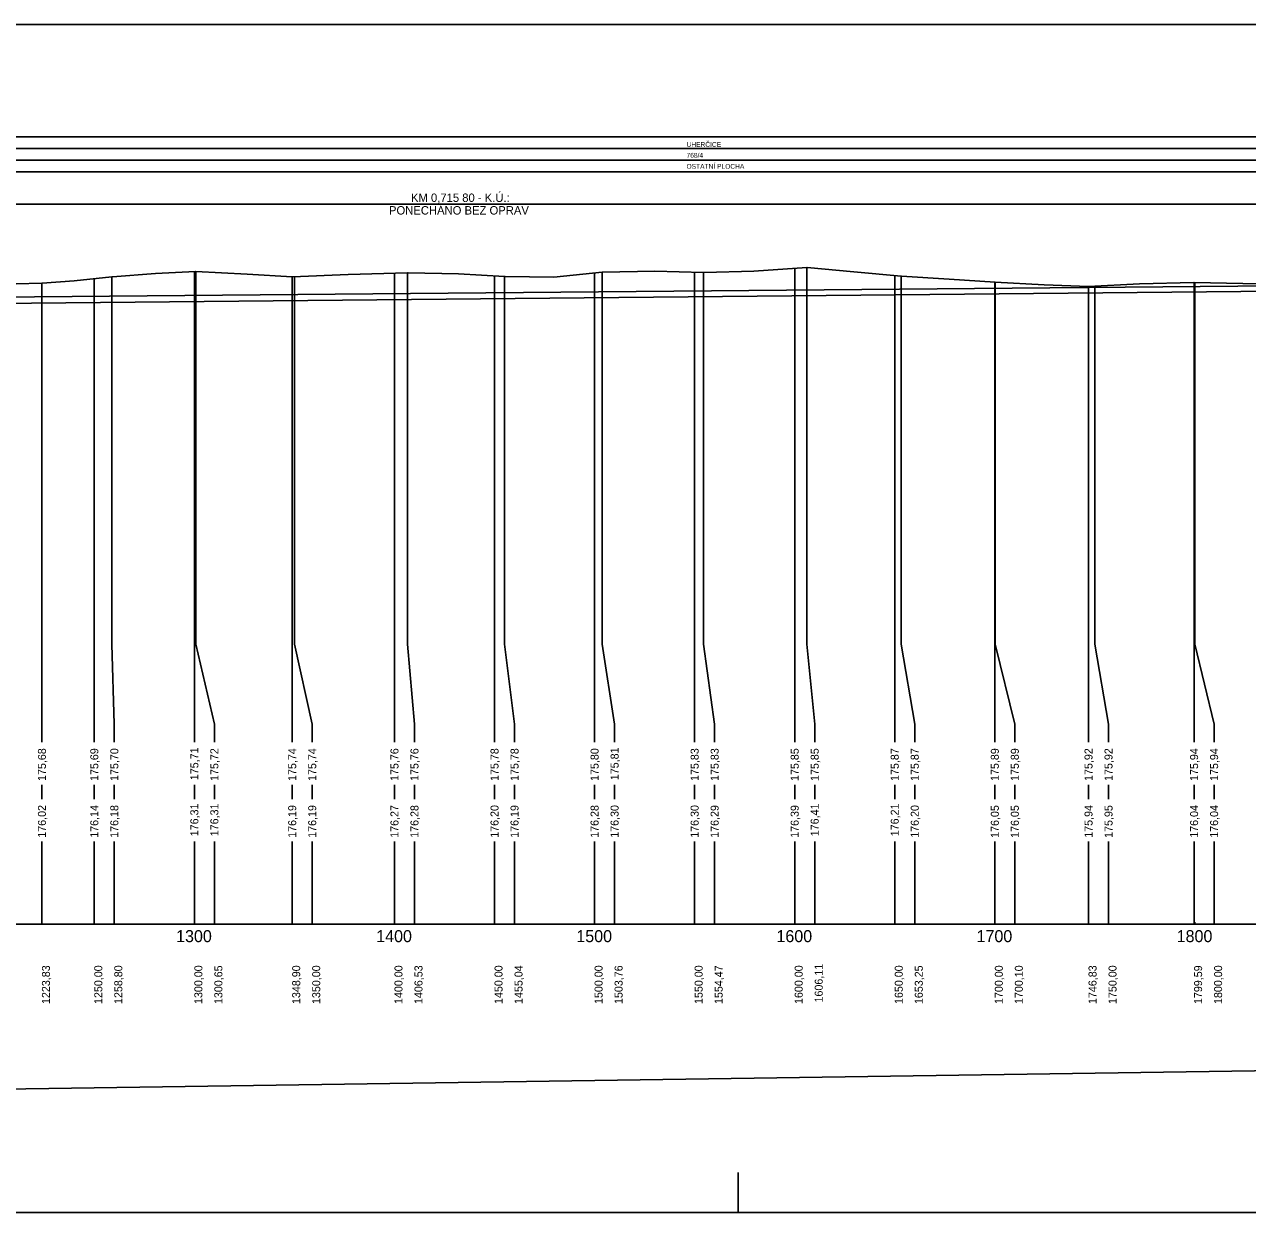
# Model space of a CAD drawing. Extents: x -614174 to -599765, y -1185887 to -1181080.
# Drawn here: x -608011 to -607400, y -1183702 to -1183108 of the extents above; entities that cross this region are included whole.
import ezdxf

# ---------------------------------------------------------------- set-up
doc = ezdxf.new("R2010")
doc.units = 0
for name, color, linetype in [('11', 7, 'Continuous'), ('13', 7, 'Continuous'), ('56', 7, 'Continuous'), ('návrh', 7, 'Continuous')]:
    doc.layers.add(name, color=color, linetype=linetype)

msp = doc.modelspace()

# ---------------------------------------------------------------- linework, layer by layer
msp.add_line((-609090.25, -1183253.49), (-607179.99, -1183236.32))
for points in [[(-608027.82, -1183237.6), (-608001.99, -1183236.83), (-608001.89, -1183236.82), (-607985.85, -1183235.62), (-607967.01, -1183233.66), (-607966.78, -1183233.65), (-607945.24, -1183231.99), (-607925.18, -1183231.02), (-607925.16, -1183231.02), (-607899.43, -1183232.41), (-607876.92, -1183233.61), (-607876.72, -1183233.62), (-607849.03, -1183232.47), (-607819.29, -1183231.73), (-607819.04, -1183231.72), (-607793.74, -1183232.27), (-607770.78, -1183233.5), (-607770.56, -1183233.51), (-607746.11, -1183233.92), (-607722.06, -1183231.38), (-607721.81, -1183231.39), (-607695.67, -1183230.88), (-607671.35, -1183231.53), (-607671.1, -1183231.56), (-607646.16, -1183230.78), (-607619.71, -1183229.03), (-607619.55, -1183229.02), (-607596.32, -1183231.19), (-607572.56, -1183233.41), (-607572.38, -1183233.43), (-607548.62, -1183234.94), (-607525.72, -1183236.41), (-607525.64, -1183236.42), (-607501.19, -1183237.77), (-607479.06, -1183238.53), (-607478.98, -1183238.52), (-607453.46, -1183237.26), (-607426.29, -1183236.52), (-607426.23, -1183236.52), (-607401.84, -1183236.95), (-607378.85, -1183237.32)], [(-607925.82, -1183231.05), (-607925.82, -1183417.32), (-607925.82, -1183457.32), (-607925.82, -1183466.4)], [(-607925.16, -1183231.02), (-607925.16, -1183417.32), (-607915.82, -1183457.32), (-607915.82, -1183466.4)], [(-607825.82, -1183231.89), (-607825.82, -1183417.32), (-607825.82, -1183457.32), (-607825.82, -1183466.4)], [(-607819.29, -1183231.73), (-607819.29, -1183417.32), (-607815.82, -1183457.32), (-607815.82, -1183466.4)], [(-607725.82, -1183231.78), (-607725.82, -1183417.32), (-607725.82, -1183457.32), (-607725.82, -1183466.4)], [(-607722.06, -1183231.38), (-607722.06, -1183417.32), (-607715.82, -1183457.32), (-607715.82, -1183466.4)], [(-607675.82, -1183231.41), (-607675.82, -1183417.32), (-607675.82, -1183457.32), (-607675.82, -1183466.4)], [(-607671.35, -1183231.53), (-607671.35, -1183417.32), (-607665.82, -1183457.32), (-607665.82, -1183466.4)], [(-607625.82, -1183229.44), (-607625.82, -1183417.32), (-607625.82, -1183457.32), (-607625.82, -1183466.4)], [(-607619.71, -1183229.03), (-607619.71, -1183417.32), (-607615.82, -1183457.32), (-607615.82, -1183466.4)], [(-607575.82, -1183233.1), (-607575.82, -1183417.32), (-607575.82, -1183457.32), (-607575.82, -1183466.4)], [(-608001.99, -1183236.83), (-608001.99, -1183417.32), (-608001.99, -1183457.32), (-608001.99, -1183466.4)], [(-607975.82, -1183234.58), (-607975.82, -1183417.32), (-607975.82, -1183457.32), (-607975.82, -1183466.4)], [(-607967.01, -1183233.66), (-607967.01, -1183417.32), (-607965.82, -1183457.32), (-607965.82, -1183466.4)], [(-607876.92, -1183233.61), (-607876.92, -1183417.32), (-607876.92, -1183457.32), (-607876.92, -1183466.4)], [(-607875.82, -1183233.59), (-607875.82, -1183417.32), (-607866.92, -1183457.32), (-607866.92, -1183466.4)], [(-607775.82, -1183233.23), (-607775.82, -1183417.32), (-607775.82, -1183457.32), (-607775.82, -1183466.4)], [(-607770.78, -1183233.5), (-607770.78, -1183417.32), (-607765.82, -1183457.32), (-607765.82, -1183466.4)], [(-607572.56, -1183233.41), (-607572.56, -1183417.32), (-607565.82, -1183457.32), (-607565.82, -1183466.4)], [(-607525.82, -1183236.4), (-607525.82, -1183417.32), (-607525.82, -1183457.32), (-607525.82, -1183466.4)], [(-607525.72, -1183236.41), (-607525.72, -1183417.32), (-607515.82, -1183457.32), (-607515.82, -1183466.4)], [(-607478.98, -1183238.52), (-607478.98, -1183417.32), (-607478.98, -1183457.32), (-607478.98, -1183466.4)], [(-607475.82, -1183238.37), (-607475.82, -1183417.32), (-607468.98, -1183457.32), (-607468.98, -1183466.4)], [(-607426.23, -1183236.52), (-607426.23, -1183417.32), (-607426.23, -1183457.32), (-607426.23, -1183466.4)], [(-607425.82, -1183236.53), (-607425.82, -1183417.32), (-607416.23, -1183457.32), (-607416.23, -1183466.4)], [(-608001.99, -1183487.61), (-608001.99, -1183494.77)], [(-607975.82, -1183487.61), (-607975.82, -1183494.77)], [(-607965.82, -1183487.61), (-607965.82, -1183494.77)], [(-607925.82, -1183487.61), (-607925.82, -1183494.77)], [(-607915.82, -1183487.61), (-607915.82, -1183494.77)], [(-607876.92, -1183487.61), (-607876.92, -1183494.77)], [(-607866.92, -1183487.61), (-607866.92, -1183494.77)], [(-607825.82, -1183487.61), (-607825.82, -1183494.77)], [(-607815.82, -1183487.61), (-607815.82, -1183494.77)], [(-607775.82, -1183487.61), (-607775.82, -1183494.77)], [(-607765.82, -1183487.61), (-607765.82, -1183494.77)], [(-607725.82, -1183487.61), (-607725.82, -1183494.77)], [(-607715.82, -1183487.61), (-607715.82, -1183494.77)], [(-607675.82, -1183487.61), (-607675.82, -1183494.77)], [(-607665.82, -1183487.61), (-607665.82, -1183494.77)], [(-607625.82, -1183487.61), (-607625.82, -1183494.77)], [(-607615.82, -1183487.61), (-607615.82, -1183494.77)], [(-607575.82, -1183487.61), (-607575.82, -1183494.77)], [(-607565.82, -1183487.61), (-607565.82, -1183494.77)], [(-607525.82, -1183487.61), (-607525.82, -1183494.77)], [(-607515.82, -1183487.61), (-607515.82, -1183494.77)], [(-607478.98, -1183487.61), (-607478.98, -1183494.77)], [(-607468.98, -1183487.61), (-607468.98, -1183494.77)], [(-607426.23, -1183487.61), (-607426.23, -1183494.77)], [(-607416.23, -1183487.61), (-607416.23, -1183494.77)], [(-608001.99, -1183515.97), (-608001.99, -1183557.32)], [(-607975.82, -1183515.97), (-607975.82, -1183557.32)], [(-607965.82, -1183515.97), (-607965.82, -1183557.32)], [(-607925.82, -1183515.97), (-607925.82, -1183557.32)], [(-607915.82, -1183515.97), (-607915.82, -1183557.32)], [(-607876.92, -1183515.97), (-607876.92, -1183557.32)], [(-607866.92, -1183515.97), (-607866.92, -1183557.32)], [(-607825.82, -1183515.97), (-607825.82, -1183557.32)], [(-607815.82, -1183515.97), (-607815.82, -1183557.32)], [(-607775.82, -1183515.97), (-607775.82, -1183557.32)], [(-607765.82, -1183515.97), (-607765.82, -1183557.32)], [(-607725.82, -1183515.97), (-607725.82, -1183557.32)], [(-607715.82, -1183515.97), (-607715.82, -1183557.32)], [(-607675.82, -1183515.97), (-607675.82, -1183557.32)], [(-607665.82, -1183515.97), (-607665.82, -1183557.32)], [(-607625.82, -1183515.97), (-607625.82, -1183557.32)], [(-607615.82, -1183515.97), (-607615.82, -1183557.32)], [(-607575.82, -1183515.97), (-607575.82, -1183557.32)], [(-607565.82, -1183515.97), (-607565.82, -1183557.32)], [(-607525.82, -1183515.97), (-607525.82, -1183557.32)], [(-607515.82, -1183515.97), (-607515.82, -1183557.32)], [(-607478.98, -1183515.97), (-607478.98, -1183557.32)], [(-607468.98, -1183515.97), (-607468.98, -1183557.32)], [(-607426.23, -1183515.97), (-607426.23, -1183557.32)], [(-607416.23, -1183515.97), (-607416.23, -1183557.32)], [(-609090.25, -1183655.48), (-607179.99, -1183627.48)]]:
    msp.add_lwpolyline(points)
at = {"layer": '56'}
for p, q in [((-607925.82, -1183557.32), (-607925.82, -1183556.32)), ((-607825.82, -1183557.32), (-607825.82, -1183556.32)), ((-607725.82, -1183557.32), (-607725.82, -1183556.32)), ((-607625.82, -1183557.32), (-607625.82, -1183556.32)), ((-607525.82, -1183557.32), (-607525.82, -1183556.32)), ((-607425.82, -1183557.32), (-607425.82, -1183556.32)), ((-609225.82, -1183557.32), (-607179.99, -1183557.32))]:
    msp.add_line(p, q, dxfattribs=at)
at = {"layer": 'návrh'}
for p, q in [((-609334.09, -1183107.51), (-606814.09, -1183107.51)), ((-608510.03, -1183197.3), (-607179.99, -1183197.3)), ((-607179.99, -1183238.91), (-609088.61, -1183257.39)), ((-607654.09, -1183681.52), (-607654.09, -1183701.51)), ((-609334.09, -1183701.51), (-606814.09, -1183701.51))]:
    msp.add_line(p, q, dxfattribs=at)
for points in [[(-609225.82, -1183163.7), (-607179.29, -1183163.7), (-607179.29, -1183169.54), (-609225.82, -1183169.54)], [(-609225.82, -1183169.54), (-607179.29, -1183169.54), (-607179.29, -1183175.37), (-609225.82, -1183175.37)], [(-609225.82, -1183175.37), (-607179.29, -1183175.37), (-607179.29, -1183181.21), (-609225.82, -1183181.21)]]:
    msp.add_lwpolyline(points, close=True, dxfattribs=at)

# ---------------------------------------------------------------- texts
at = {"layer": '11'}
for s, p in [('175,68', (-607999.99, -1183485.74)), ('175,69', (-607973.82, -1183485.74)), ('175,70', (-607963.82, -1183485.73)), ('175,71', (-607923.82, -1183485.35)), ('175,72', (-607913.82, -1183485.72)), ('175,74', (-607874.92, -1183485.73)), ('175,74', (-607864.92, -1183485.73)), ('175,76', (-607823.82, -1183485.74)), ('175,76', (-607813.82, -1183485.74)), ('175,78', (-607773.82, -1183485.74)), ('175,78', (-607763.82, -1183485.74)), ('175,80', (-607723.82, -1183485.73)), ('175,81', (-607713.82, -1183485.35)), ('175,83', (-607673.82, -1183485.74)), ('175,83', (-607663.82, -1183485.74)), ('175,85', (-607623.82, -1183485.75)), ('175,85', (-607613.82, -1183485.75)), ('175,87', (-607573.82, -1183485.74)), ('175,87', (-607563.82, -1183485.74)), ('175,89', (-607523.82, -1183485.74)), ('175,89', (-607513.82, -1183485.74)), ('175,92', (-607476.98, -1183485.72)), ('175,92', (-607466.98, -1183485.72)), ('175,94', (-607424.23, -1183485.73)), ('175,94', (-607414.23, -1183485.73)), ('176,02', (-607999.99, -1183514.11)), ('176,14', (-607973.82, -1183514.14)), ('176,18', (-607963.82, -1183514.16)), ('176,31', (-607923.82, -1183513.38)), ('176,31', (-607913.82, -1183513.38)), ('176,19', (-607874.92, -1183514.16)), ('176,19', (-607864.92, -1183514.16)), ('176,27', (-607823.82, -1183514.16)), ('176,28', (-607813.82, -1183514.16)), ('176,20', (-607773.82, -1183514.14)), ('176,19', (-607763.82, -1183514.16)), ('176,28', (-607723.82, -1183514.16)), ('176,30', (-607713.82, -1183514.14)), ('176,30', (-607673.82, -1183514.14)), ('176,29', (-607663.82, -1183514.16)), ('176,39', (-607623.82, -1183514.16)), ('176,41', (-607613.82, -1183513.38)), ('176,21', (-607573.82, -1183513.38)), ('176,20', (-607563.82, -1183514.14)), ('176,05', (-607523.82, -1183514.19)), ('176,05', (-607513.82, -1183514.19)), ('175,94', (-607476.98, -1183514.14)), ('175,95', (-607466.98, -1183514.19)), ('176,04', (-607424.23, -1183514.14)), ('176,04', (-607414.23, -1183514.14)), ('1223,83', (-607997.99, -1183597.26)), ('1250,00', (-607971.82, -1183597.25)), ('1258,80', (-607961.82, -1183597.25)), ('1300,00', (-607921.82, -1183597.25)), ('1300,65', (-607911.82, -1183597.29)), ('1348,90', (-607872.92, -1183597.25)), ('1350,00', (-607862.92, -1183597.25)), ('1400,00', (-607821.82, -1183597.25)), ('1406,53', (-607811.82, -1183597.26)), ('1450,00', (-607771.82, -1183597.25)), ('1455,04', (-607761.82, -1183597.24)), ('1500,00', (-607721.82, -1183597.25)), ('1503,76', (-607711.82, -1183597.26)), ('1550,00', (-607671.82, -1183597.25)), ('1554,47', (-607661.82, -1183597.26)), ('1600,00', (-607621.82, -1183597.25)), ('1606,11', (-607611.82, -1183596.49)), ('1650,00', (-607571.82, -1183597.25)), ('1653,25', (-607561.82, -1183597.29)), ('1700,00', (-607521.82, -1183597.25)), ('1700,10', (-607511.82, -1183597.25)), ('1746,83', (-607474.98, -1183597.26)), ('1750,00', (-607464.98, -1183597.25)), ('1799,59', (-607422.23, -1183597.27)), ('1800,00', (-607412.23, -1183597.25))]:
    msp.add_text(s, height=4, rotation=90, dxfattribs=at).set_placement(p)
at = {"layer": '13'}
for s, height, p in [('UHERČICE', 2.4, (-607679.88, -1183168.71)), ('768/4', 2.4, (-607679.88, -1183174.13)), ('OSTATNÍ PLOCHA', 2.4, (-607679.88, -1183179.66)), ('KM 0,715 80 - K.Ú.: ', 4.2, (-607817.56, -1183196.24)), ('PONECHÁNO BEZ OPRAV', 4.2, (-607828.56, -1183202.54)), ('1300', 6, (-607934.94, -1183566.32)), ('1400', 6, (-607834.94, -1183566.32)), ('1500', 6, (-607734.94, -1183566.32)), ('1600', 6, (-607634.94, -1183566.32)), ('1700', 6, (-607534.94, -1183566.32)), ('1800', 6, (-607434.94, -1183566.32))]:
    msp.add_text(s, height=height, dxfattribs=at).set_placement(p)

doc.saveas('drawing.dxf')
